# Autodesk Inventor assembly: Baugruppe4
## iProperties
Created: 2004-09
Part Number: Baugruppe4
Document SubType Name: Assembly
Designer: W. Holzwarth
Manufacturer: Standard
Standards Organization: Custom
Author: W. Holzwarth
